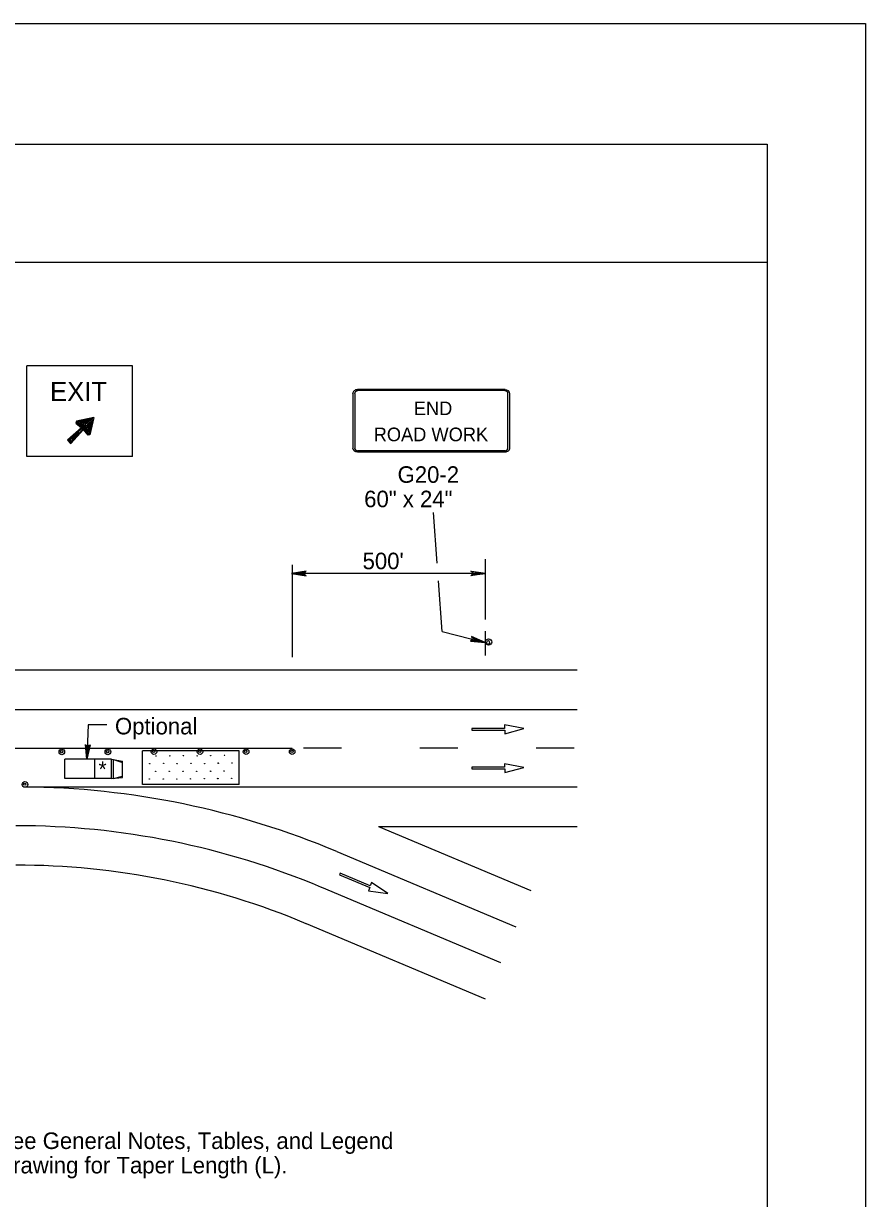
# Model space of a CAD drawing. Extents: x -14145 to -13662, y 30244 to 30661.
# Drawn here: x -13801.86 to -13791.17, y 30300.39 to 30315.31 of the extents above; entities that cross this region are included whole.
import ezdxf

# ---------------------------------------------------------------- set-up
doc = ezdxf.new("R2010")
doc.units = 0
for name, color, linetype in [('1', 7, 'Continuous'), ('10', 7, 'Continuous'), ('2', 7, 'Continuous'), ('61', 7, 'Continuous')]:
    doc.layers.add(name, color=color, linetype=linetype)

msp = doc.modelspace()

# ---------------------------------------------------------------- linework, layer by layer
at = {"layer": '1'}
for p, q in [((-13801.817, 30309.808), (-13801.817, 30310.96)), ((-13800.473, 30310.96), (-13801.817, 30310.96)), ((-13800.473, 30309.808), (-13800.473, 30310.96)), ((-13795.746, 30310.661), (-13797.619, 30310.661)), ((-13795.746, 30310.661), (-13797.619, 30310.661)), ((-13797.68, 30310.61), (-13797.68, 30309.922)), ((-13797.655, 30310.61), (-13797.655, 30309.922)), ((-13795.746, 30310.646), (-13797.619, 30310.646)), ((-13795.746, 30310.646), (-13797.619, 30310.646)), ((-13795.71, 30309.922), (-13795.71, 30310.61)), ((-13795.685, 30309.922), (-13795.685, 30310.61)), ((-13801.187, 30310.258), (-13801.193, 30310.234)), ((-13801.193, 30310.234), (-13801.121, 30310.174)), ((-13800.965, 30310.306), (-13801.187, 30310.258)), ((-13801.179, 30310.249), (-13801.182, 30310.238)), ((-13801.182, 30310.238), (-13801.105, 30310.174)), ((-13800.978, 30310.293), (-13801.179, 30310.249)), ((-13800.992, 30310.28), (-13801.17, 30310.241)), ((-13801.17, 30310.241), (-13801.097, 30310.18)), ((-13801.005, 30310.267), (-13801.148, 30310.235)), ((-13801.148, 30310.235), (-13801.09, 30310.187)), ((-13801.019, 30310.254), (-13801.126, 30310.23)), ((-13801.126, 30310.23), (-13801.083, 30310.194)), ((-13801.032, 30310.241), (-13801.104, 30310.225)), ((-13801.104, 30310.225), (-13801.076, 30310.201)), ((-13801.046, 30310.228), (-13801.081, 30310.22)), ((-13801.081, 30310.22), (-13801.071, 30310.211)), ((-13801.046, 30310.228), (-13801.054, 30310.191)), ((-13801.032, 30310.241), (-13801.049, 30310.168)), ((-13801.019, 30310.254), (-13801.043, 30310.146)), ((-13801.005, 30310.267), (-13801.037, 30310.124)), ((-13800.992, 30310.28), (-13801.032, 30310.102)), ((-13800.978, 30310.293), (-13801.024, 30310.093)), ((-13800.965, 30310.306), (-13801.015, 30310.084)), ((-13801.121, 30310.174), (-13801.301, 30310.018)), ((-13801.105, 30310.174), (-13801.286, 30310.017)), ((-13801.154, 30310.117), (-13801.271, 30310.016)), ((-13801.098, 30310.166), (-13801.258, 30309.985)), ((-13801.154, 30310.117), (-13801.257, 30310.001)), ((-13801.098, 30310.151), (-13801.256, 30309.973)), ((-13801.035, 30310.09), (-13801.098, 30310.166)), ((-13801.039, 30310.079), (-13801.098, 30310.151)), ((-13801.032, 30310.102), (-13801.097, 30310.18)), ((-13801.037, 30310.124), (-13801.09, 30310.187)), ((-13801.043, 30310.146), (-13801.083, 30310.194)), ((-13801.049, 30310.168), (-13801.076, 30310.201)), ((-13801.054, 30310.191), (-13801.071, 30310.211)), ((-13801.015, 30310.084), (-13801.039, 30310.079)), ((-13801.024, 30310.093), (-13801.035, 30310.09)), ((-13801.301, 30310.018), (-13801.259, 30309.97)), ((-13801.286, 30310.017), (-13801.258, 30309.985)), ((-13801.271, 30310.016), (-13801.257, 30310.001)), ((-13800.473, 30309.808), (-13801.817, 30309.808)), ((-13797.619, 30309.885), (-13795.746, 30309.885)), ((-13797.619, 30309.87), (-13795.746, 30309.87)), ((-13796.659, 30309.099), (-13796.612, 30308.457)), ((-13798.449, 30308.435), (-13798.449, 30307.262)), ((-13795.995, 30307.74), (-13795.995, 30308.507)), ((-13795.994, 30308.326), (-13798.459, 30308.326)), ((-13796.595, 30308.232), (-13796.548, 30307.589)), ((-13796.547, 30307.589), (-13796, 30307.449)), ((-13795.994, 30307.282), (-13795.994, 30307.594)), ((-13795.994, 30307.282), (-13795.994, 30307.594)), ((-13821.919, 30307.1), (-13794.831, 30307.1)), ((-13821.919, 30306.6), (-13794.831, 30306.6)), ((-13795.754, 30306.357), (-13796.168, 30306.357)), ((-13796.168, 30306.357), (-13796.168, 30306.335)), ((-13796.168, 30306.335), (-13795.751, 30306.335)), ((-13795.51, 30306.356), (-13795.754, 30306.402)), ((-13795.754, 30306.402), (-13795.754, 30306.357)), ((-13795.751, 30306.29), (-13795.51, 30306.356)), ((-13795.751, 30306.335), (-13795.751, 30306.29)), ((-13803.124, 30306.107), (-13798.449, 30306.107)), ((-13799.122, 30306.072), (-13800.346, 30306.072)), ((-13800.346, 30305.646), (-13800.346, 30306.072)), ((-13799.122, 30305.646), (-13799.122, 30306.072)), ((-13797.823, 30306.108), (-13798.303, 30306.108)), ((-13796.347, 30306.108), (-13796.827, 30306.108)), ((-13794.871, 30306.108), (-13795.351, 30306.108)), ((-13801.335, 30305.722), (-13801.335, 30305.968)), ((-13800.741, 30305.968), (-13801.335, 30305.968)), ((-13800.951, 30305.722), (-13800.951, 30305.968)), ((-13800.741, 30305.722), (-13800.741, 30305.968)), ((-13800.741, 30305.968), (-13800.603, 30305.944)), ((-13800.717, 30305.962), (-13800.603, 30305.926)), ((-13800.717, 30305.722), (-13800.717, 30305.962)), ((-13800.603, 30305.734), (-13800.603, 30305.944)), ((-13795.51, 30305.864), (-13795.754, 30305.91)), ((-13795.754, 30305.91), (-13795.754, 30305.865)), ((-13800.717, 30305.722), (-13800.603, 30305.752)), ((-13795.754, 30305.865), (-13796.168, 30305.865)), ((-13796.168, 30305.865), (-13796.168, 30305.843)), ((-13796.168, 30305.843), (-13795.751, 30305.843)), ((-13795.751, 30305.798), (-13795.51, 30305.864)), ((-13795.751, 30305.843), (-13795.751, 30305.798)), ((-13801.858, 30305.615), (-13794.831, 30305.615)), ((-13800.741, 30305.722), (-13801.335, 30305.722)), ((-13800.741, 30305.722), (-13800.603, 30305.734)), ((-13799.122, 30305.646), (-13800.346, 30305.646)), ((-13797.355, 30305.115), (-13794.831, 30305.115)), ((-13797.355, 30305.115), (-13795.418, 30304.301)), ((-13797.881, 30304.794), (-13795.612, 30303.84)), ((-13797.84, 30304.519), (-13797.849, 30304.499)), ((-13797.849, 30304.499), (-13797.465, 30304.338)), ((-13797.458, 30304.359), (-13797.84, 30304.519)), ((-13797.441, 30304.401), (-13797.458, 30304.359)), ((-13797.234, 30304.264), (-13797.441, 30304.401)), ((-13798.076, 30304.341), (-13795.804, 30303.385)), ((-13797.465, 30304.338), (-13797.482, 30304.296)), ((-13797.482, 30304.296), (-13797.234, 30304.264)), ((-13798.27, 30303.88), (-13795.998, 30302.924))]:
    msp.add_line(p, q, dxfattribs=at)
for points in [[(-13798.279, 30308.35), (-13798.291, 30308.332), (-13798.459, 30308.326), (-13798.279, 30308.35), (-13798.273, 30308.356), (-13798.459, 30308.326), (-13798.291, 30308.314), (-13798.279, 30308.302), (-13798.459, 30308.326), (-13798.273, 30308.296), (-13798.279, 30308.302)], [(-13796.174, 30308.35), (-13796.162, 30308.332), (-13795.994, 30308.326), (-13796.174, 30308.35), (-13796.18, 30308.356), (-13795.994, 30308.326), (-13796.162, 30308.314), (-13796.174, 30308.302), (-13795.994, 30308.326), (-13796.18, 30308.296), (-13796.174, 30308.302)], [(-13796.18, 30307.473), (-13796.168, 30307.485), (-13796, 30307.449), (-13796.18, 30307.473), (-13796.186, 30307.467), (-13796, 30307.449), (-13796.162, 30307.503), (-13796.168, 30307.515), (-13796, 30307.449), (-13796.174, 30307.527), (-13796.168, 30307.515)], [(-13800.801, 30306.403), (-13801.037, 30306.403), (-13801.055, 30305.968)], [(-13801.026, 30306.14), (-13801.038, 30306.134), (-13801.055, 30305.968), (-13801.026, 30306.14), (-13801.013, 30306.15), (-13801.055, 30305.968), (-13801.056, 30306.136), (-13801.067, 30306.142), (-13801.055, 30305.968), (-13801.073, 30306.156), (-13801.067, 30306.142)]]:
    msp.add_lwpolyline(points, dxfattribs=at)
for centre, radius in [((-13795.956, 30307.455), 0.0408), ((-13801.371, 30306.06), 0.0354), ((-13801.374, 30306.063), 0.0143), ((-13800.787, 30306.06), 0.0354), ((-13800.79, 30306.063), 0.0143), ((-13800.202, 30306.063), 0.0354), ((-13800.206, 30306.066), 0.0143), ((-13799.618, 30306.063), 0.0354), ((-13799.621, 30306.066), 0.0143), ((-13799.033, 30306.063), 0.0354), ((-13799.037, 30306.066), 0.0143), ((-13798.449, 30306.063), 0.0354), ((-13798.452, 30306.066), 0.0143), ((-13800.255, 30305.911), 0.00272), ((-13800.175, 30306.009), 0.00272), ((-13800.08, 30305.914), 0.00272), ((-13800.002, 30306.01), 0.00272), ((-13799.908, 30305.911), 0.00272), ((-13799.828, 30306.012), 0.00272), ((-13799.732, 30305.914), 0.00272), ((-13799.653, 30306.01), 0.00272), ((-13799.559, 30305.912), 0.00272), ((-13799.482, 30306.013), 0.00272), ((-13799.387, 30305.917), 0.00272), ((-13799.385, 30305.915), 0.00272), ((-13799.307, 30306.015), 0.00272), ((-13799.212, 30305.92), 0.00272), ((-13800.18, 30305.813), 0.00272), ((-13800.009, 30305.813), 0.00272), ((-13799.832, 30305.814), 0.00272), ((-13799.659, 30305.814), 0.00272), ((-13799.483, 30305.815), 0.00272), ((-13799.312, 30305.819), 0.00272), ((-13801.839, 30305.647), 0.0354), ((-13801.842, 30305.65), 0.0143), ((-13800.26, 30305.716), 0.00272), ((-13800.085, 30305.717), 0.00272), ((-13799.912, 30305.717), 0.00272), ((-13799.738, 30305.718), 0.00272), ((-13799.564, 30305.719), 0.00272), ((-13799.392, 30305.722), 0.00272), ((-13799.391, 30305.719), 0.00272), ((-13799.217, 30305.723), 0.00272)]:
    msp.add_circle(centre, radius, dxfattribs=at)
for centre, radius, start, end in [((-13795.961, 30307.447), 0.0214, 175.7499, 170.479), ((-13801.95, 30295.122), 10.494, 67.1811, 89.4877), ((-13801.954, 30295.123), 10, 67.1811, 90), ((-13801.954, 30295.123), 9.5, 67.1811, 90)]:
    msp.add_arc(centre, radius, start, end, dxfattribs=at)
for centre, major_axis, ratio, start_param, end_param in [((-13797.62, 30310.607), (0.0609, 0), 0.839899, 1.570796, 3.141593), ((-13797.62, 30310.607), (0, -0.0365), 0.999938, 3.141593, 4.712389), ((-13795.747, 30310.607), (-0.0609, 0), 0.839899, 3.141593, 4.712389), ((-13795.747, 30310.607), (0, 0.0365), 0.999938, 4.712389, 6.283185), ((-13797.62, 30309.92), (0.0609, 0), 0.839899, 3.141593, 4.712389), ((-13797.62, 30309.92), (0, -0.0365), 0.999938, 4.712389, 6.283185), ((-13795.747, 30309.92), (0, 0.0365), 0.999938, 3.141593, 4.712389), ((-13795.747, 30309.92), (-0.0609, 0), 0.839899, 1.570796, 3.141593)]:
    msp.add_ellipse(centre, major_axis=major_axis, ratio=ratio, start_param=start_param, end_param=end_param, dxfattribs=at)
at = {"layer": '10'}
for p, q in [((-13823.874, 30313.777), (-13792.422, 30313.777)), ((-13792.422, 30313.777), (-13792.422, 30291.207)), ((-13823.874, 30312.277), (-13792.422, 30312.277))]:
    msp.add_line(p, q, dxfattribs=at)
at = {"layer": '61'}
msp.add_lwpolyline([(-13824.174, 30315.307), (-13791.174, 30315.307), (-13791.174, 30289.807), (-13824.174, 30289.807)], close=True, dxfattribs=at)

# ---------------------------------------------------------------- texts
at = {"layer": '1'}
for s, height, p in [('EXIT', 0.2431, (-13801.521, 30310.514)), ('END', 0.173, (-13796.905, 30310.335)), ('ROAD WORK', 0.173, (-13797.414, 30310.004))]:
    msp.add_text(s, height=height, dxfattribs=at).set_placement(p)
msp.add_text('*', height=0.198, rotation=0.7233, dxfattribs=at).set_placement((-13800.904, 30305.741))
at = {"layer": '2'}
for s, p in [('G20-2', (-13797.111, 30309.476)), ('60" x 24"', (-13797.535, 30309.166)), ("500'", (-13797.555, 30308.379)), ('Optional', (-13800.697, 30306.282)), ('See General Notes, Tables, and Legend ', (-13802.192, 30301.019)), ('Drawing for Taper Length (L).', (-13802.192, 30300.709))]:
    msp.add_text(s, height=0.21, dxfattribs=at).set_placement(p)

doc.saveas('drawing.dxf')
